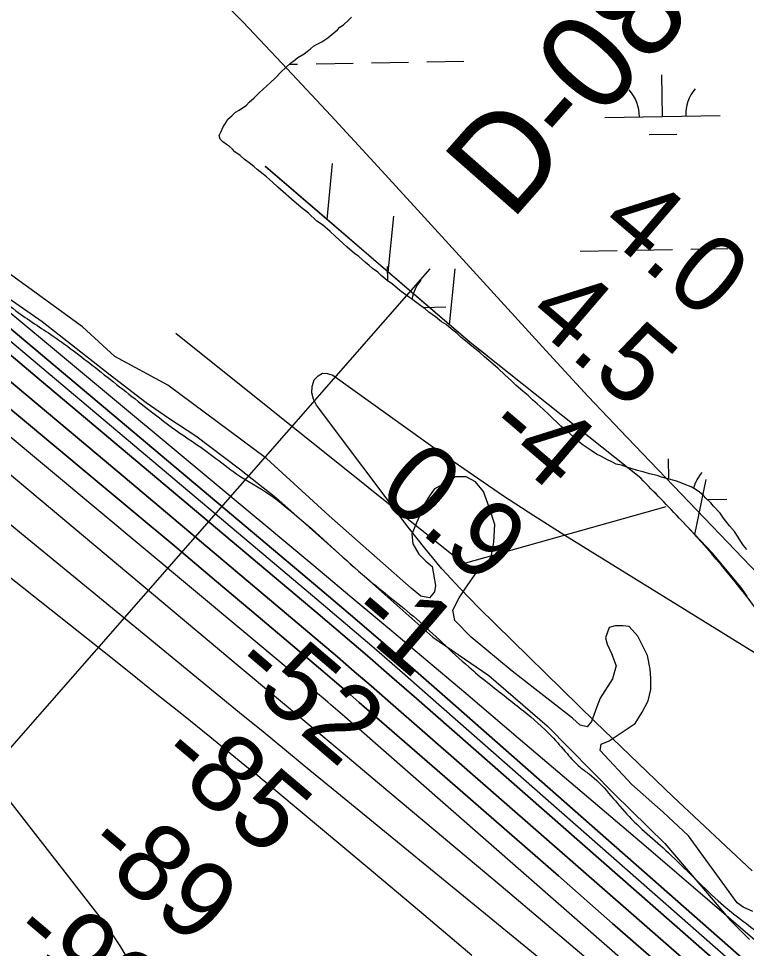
# Model space of a CAD drawing. Extents: x 3887375 to 3925618, y 296674 to 322633.
# Drawn here: x 3894675 to 3895306, y 313327 to 314133 of the extents above; entities that cross this region are included whole.
import ezdxf

# ---------------------------------------------------------------- set-up
doc = ezdxf.new("R2010")
doc.units = 0
for name, color, linetype in [('V-RIVR-EDGE', 7, 'Continuous'), ('V-RIVR-JETY', 7, 'Continuous'), ('V-RIVR-RANG', 7, 'Continuous'), ('V-RIVR-RANG-IDEN', 7, 'Continuous'), ('V-RRAP-FSHR', 7, 'Continuous'), ('V-TOPO-DPTH', 7, 'Continuous'), ('V-TOPO-MAJR', 7, 'Continuous'), ('V-TOPO-MINR', 7, 'Continuous'), ('V-TOPO-SHOR', 7, 'Continuous'), ('V-TOPO-WATR', 7, 'Continuous'), ('V-WETL-SWMP', 7, 'Continuous')]:
    doc.layers.add(name, color=color, linetype=linetype)

msp = doc.modelspace()

# ---------------------------------------------------------------- linework, layer by layer
at = {"layer": 'V-RIVR-EDGE'}
msp.add_spline([(3894279.09, 314238.38), (3894300.17, 314224.38), (3894318.47, 314210.78), (3894328.81, 314199.99), (3894339.15, 314192.4), (3894356.26, 314181.59), (3894374.58, 314173.98), (3894382.14, 314170.37), (3894386.51, 314164.78), (3894397.24, 314152.8), (3894405.19, 314145.6), (3894434.57, 314098.11), (3894440.9, 314079.36), (3894452.8, 314055.82), (3894469.08, 314031.46), (3894480.99, 314016.69), (3894492.13, 314006.3), (3894499.69, 314002.3), (3894505.66, 313998.3), (3894516.39, 313986.31), (3894533.5, 313973.92), (3894554.19, 313961.11), (3894576.07, 313946.71), (3894604.32, 313925.52), (3894627, 313911.51), (3894651.27, 313896.71), (3894673.15, 313879.52), (3894705.37, 313857.52), (3894744.36, 313828.33), (3894786.92, 313794.75), (3894815.16, 313773.55), (3894843.81, 313753.56), (3894864.49, 313737.96), (3894892.75, 313720.36), (3894906.27, 313709.96), (3894922.58, 313696.37), (3894976.66, 313648.01), (3895020.01, 313612.44), (3895065.34, 313570.88), (3895097.95, 313544.49), (3895112.67, 313532.9), (3895136.93, 313510.92), (3895150.44, 313495.74), (3895161.57, 313484.16), (3895169.53, 313478.16), (3895202.12, 313443.41), (3895238.3, 313409.84), (3895281.24, 313368.29), (3895321.02, 313337.1), (3895346.88, 313317.51), (3895405.32, 313261.97), (3895426, 313241.2), (3895440.7, 313224.82), (3895449.44, 313212.44)], degree=3, dxfattribs=at)
at = {"layer": 'V-RIVR-JETY'}
for points in [[(3895311.45, 313358.88), (3895303.14, 313362.65), (3895297.85, 313366.43), (3895255.56, 313424.58), (3895233.66, 313444.96), (3895206.48, 313469.13), (3895179.29, 313498.58), (3895180.05, 313503.87), (3895186.84, 313506.89), (3895209.5, 313521.99), (3895215.54, 313531.81), (3895220.83, 313541.63), (3895223.09, 313551.44), (3895223.09, 313561.26), (3895222.34, 313568.81), (3895220.07, 313580.89), (3895211.76, 313597.51), (3895204.21, 313605.81), (3895198.93, 313606.57), (3895192.13, 313606.57), (3895186.84, 313605.06), (3895183.82, 313596), (3895185.33, 313590.71), (3895189.11, 313582.4), (3895192.88, 313571.83), (3895189.86, 313560.5), (3895179.29, 313543.89), (3895176.27, 313536.34), (3895171.74, 313523.5), (3895167.96, 313518.97), (3895161.92, 313520.48), (3895155.13, 313526.52), (3895103.02, 313567.3), (3895067.53, 313596.75), (3895053.18, 313611.1), (3895051.67, 313620.16), (3895056.96, 313630.74), (3895064.51, 313642.06), (3895072.06, 313652.63), (3895081.12, 313659.43), (3895084.9, 313667.74), (3895087.16, 313679.07), (3895087.92, 313694.17), (3895083.39, 313708.52), (3895078.1, 313722.87), (3895071.3, 313731.17), (3895063, 313735.7), (3895053.93, 313735.7), (3895041.1, 313728.15), (3895035.81, 313725.13), (3895031.28, 313719.09), (3895026.75, 313711.54), (3895024.48, 313705.5), (3895019.95, 313695.68), (3895016.18, 313685.86), (3895016.93, 313677.56), (3895022.22, 313668.49), (3895028.26, 313662.45), (3895033.55, 313657.92), (3895036.57, 313641.31), (3895035.81, 313636.02), (3895031.28, 313630.74), (3895023.73, 313632.25), (3895015.42, 313639.04), (3894944.44, 313701.72), (3894890.06, 313751.56), (3894804.73, 313814.99), (3894758.67, 313839.92), (3894730.72, 313865.59), (3894535.14, 314007.56)], [(3894557.79, 313966.03), (3894695.99, 313870.12), (3894754.89, 313824.06), (3894785.85, 313799.89), (3894805.49, 313786.3), (3894828.9, 313771.2), (3894866.65, 313742.5), (3894898.37, 313717.58), (3894987.48, 313638.29), (3895034.3, 313596.75), (3895056.2, 313581.65), (3895082.63, 313563.53), (3895133.23, 313519.73), (3895191.37, 313460.82), (3895235.17, 313417.78), (3895265.38, 313382.29), (3895291.81, 313351.32), (3895308.42, 313334.71)]]:
    msp.add_lwpolyline(points, dxfattribs=at)
at = {"layer": 'V-RIVR-RANG'}
msp.add_line((3895031.53, 313915.92), (3894557.25, 313374.2), dxfattribs=at)
at = {"layer": 'V-RRAP-FSHR'}
for p, q in [((3894942.57, 313958.54), (3894947.39, 314007.13)), ((3894995.68, 313912.93), (3895000.49, 313961.52)), ((3895048.78, 313867.33), (3895053.59, 313915.92)), ((3895261.17, 313685.55), (3895271.06, 313733.37))]:
    msp.add_line(p, q, dxfattribs=at)
for points in [[(3895214.31, 313734.34), (3895066.45, 313852.15), (3894888.92, 314004.62)], [(3894889.47, 314004.14), (3894888.92, 314004.62)], [(3894942.57, 313958.54), (3894889.47, 314004.15)], [(3894995.68, 313912.93), (3894942.57, 313958.54)], [(3895081.27, 313840.34), (3895066.45, 313852.15), (3895048.78, 313867.33), (3894995.67, 313912.93)], [(3894811.5, 313860.16), (3895060.76, 313660.4), (3895236.38, 313709.88)], [(3895261.17, 313685.55), (3895249.53, 313697.9), (3895231.92, 313716.12), (3895224.84, 313723.44)], [(3895306.48, 313632.29), (3895300.99, 313640.09), (3895276.1, 313669.72), (3895261.17, 313685.56)]]:
    msp.add_lwpolyline(points, dxfattribs=at)
msp.add_spline([(3895382.66, 313514.85), (3895315.81, 313619.05), (3895249.53, 313697.9), (3895214.31, 313734.34)], degree=3, dxfattribs=at)
at = {"layer": 'V-TOPO-DPTH'}
for points in [[(3895356.45, 313608.97), (3895202.61, 313769.6), (3895185.66, 313787.43), (3895168.79, 313805.34), (3895152.06, 313823.38), (3895135.42, 313841.49), (3895020.97, 313966.99), (3894983.49, 314007.86), (3894945.86, 314048.59), (3894907.99, 314089.11), (3894869.98, 314129.49), (3894830.99, 314168.81), (3894790.87, 314206.89), (3894621.93, 314337.77), (3894383.23, 314448.72), (3894091.96, 314544.03), (3893867.05, 314583.12), (3893838.43, 314605.12), (3893809.72, 314626.99), (3893780.94, 314648.78), (3893286.1, 315021.75), (3893269.81, 315033.97), (3893253.49, 315046.13)], [(3895305.16, 313270.77), (3895231.56, 313335.34), (3895157.88, 313399.81), (3894995.3, 313541.84), (3894980.78, 313554.46), (3894966.21, 313567.04), (3894951.59, 313579.53), (3894936.92, 313591.98), (3894833.93, 313678.9), (3894767.68, 313734.72), (3894701.37, 313790.45), (3894634.96, 313846.06), (3894568.48, 313901.59), (3894415.94, 314028.77), (3894397.05, 314044.56), (3894378.18, 314060.37), (3894359.34, 314076.22), (3894340.52, 314092.09), (3893865.37, 314493.75)], [(3893865.37, 314493.75), (3894340.52, 314092.09), (3894359.34, 314076.22), (3894378.18, 314060.37), (3894397.05, 314044.56), (3894415.94, 314028.77), (3894568.48, 313901.59), (3894634.96, 313846.06), (3894701.37, 313790.45), (3894767.68, 313734.72), (3894833.93, 313678.9), (3894936.92, 313591.98), (3894951.59, 313579.53), (3894966.21, 313567.04), (3894980.78, 313554.46), (3894995.3, 313541.84), (3895157.88, 313399.81), (3895231.56, 313335.34), (3895305.16, 313270.77)], [(3895236.78, 313307.47), (3895189.92, 313348.65), (3895143.02, 313389.78), (3895096.04, 313430.82), (3895049.01, 313471.8), (3894970.56, 313540.04), (3894962.7, 313546.84), (3894954.82, 313553.63), (3894946.91, 313560.38), (3894938.99, 313567.11), (3894882.83, 313614.59), (3894846.78, 313645.01), (3894810.69, 313675.38), (3894774.54, 313705.68), (3894738.35, 313735.93), (3894417.97, 314003.19), (3894392.02, 314024.83), (3894366.08, 314046.48), (3894340.14, 314068.13), (3894314.2, 314089.78), (3894102.47, 314266.53)], [(3894102.47, 314266.53), (3894314.2, 314089.78), (3894340.14, 314068.13), (3894366.08, 314046.48), (3894392.02, 314024.83), (3894417.97, 314003.19), (3894738.35, 313735.93), (3894774.54, 313705.68), (3894810.69, 313675.38), (3894846.78, 313645.01), (3894882.83, 313614.59), (3894938.99, 313567.11), (3894946.91, 313560.38), (3894954.82, 313553.63), (3894962.7, 313546.84), (3894970.56, 313540.04), (3895049.01, 313471.8), (3895096.04, 313430.82), (3895143.02, 313389.78), (3895189.92, 313348.65), (3895236.78, 313307.47)], [(3894208.2, 314229.17), (3894366.18, 314094.17), (3894378.08, 314084.04), (3894390.01, 314073.95), (3894401.97, 314063.9), (3894413.96, 314053.88), (3894491.91, 313989), (3894542.85, 313946.52), (3894593.74, 313903.97), (3894644.56, 313861.34), (3894695.32, 313818.64), (3894934.83, 313616.82), (3894956.24, 313598.66), (3894977.59, 313580.42), (3894998.83, 313562.05), (3895019.99, 313543.6), (3895384.8, 313223.59)], [(3894208.2, 314229.17), (3894366.18, 314094.17), (3894378.08, 314084.04), (3894390.01, 314073.95), (3894401.97, 314063.9), (3894413.96, 314053.88), (3894491.91, 313989), (3894542.85, 313946.52), (3894593.74, 313903.97), (3894644.56, 313861.34), (3894695.32, 313818.64), (3894934.83, 313616.82), (3894956.24, 313598.66), (3894977.59, 313580.42), (3894998.83, 313562.05), (3895019.99, 313543.6), (3895384.8, 313223.59)], [(3895602.02, 313054.44), (3895044.64, 313545.3), (3895016.85, 313569.61), (3894988.95, 313593.79), (3894960.89, 313617.78), (3894932.72, 313641.65), (3894530.51, 313980.01), (3894509.11, 313997.98), (3894487.68, 314015.92), (3894466.23, 314033.83), (3894444.75, 314051.71), (3894411.96, 314078.96), (3894406.87, 314083.21), (3894401.8, 314087.48), (3894396.75, 314091.78), (3894391.72, 314096.09), (3894339.08, 314141.49)], [(3894339.08, 314141.49), (3894391.72, 314096.09), (3894396.75, 314091.78), (3894401.8, 314087.48), (3894406.87, 314083.21), (3894411.96, 314078.96), (3894444.75, 314051.71), (3894466.23, 314033.83), (3894487.68, 314015.92), (3894509.11, 313997.98), (3894530.51, 313980.01), (3894932.72, 313641.65), (3894960.89, 313617.78), (3894988.95, 313593.79), (3895016.85, 313569.61), (3895044.64, 313545.3), (3895602.02, 313054.44)], [(3895310.83, 313394.26), (3895242.38, 313458.37), (3895174.76, 313523.38), (3895074.02, 313622.15), (3895057.79, 313638.8), (3895042.09, 313655.91), (3895027.19, 313673.72), (3895012.82, 313691.99), (3894933.47, 313797.74), (3894930.8, 313803.01), (3894929.36, 313808.39), (3894929.77, 313813.94), (3894931.41, 313819.61), (3894934.79, 313823.25), (3894938.54, 313825.39), (3894942.86, 313825.28), (3894947.56, 313823.68), (3895043.48, 313755.06), (3895069.32, 313736.96), (3895095.4, 313719.22), (3895121.82, 313702), (3895148.48, 313685.14), (3895349.93, 313560.54)]]:
    msp.add_lwpolyline(points, dxfattribs=at)
at = {"layer": 'V-TOPO-MAJR'}
msp.add_lwpolyline([(3895553.31, 313005.87), (3894986.85, 313502.45), (3894979.63, 313508.77), (3894972.4, 313515.07), (3894965.16, 313521.37), (3894957.92, 313527.65), (3894945.77, 313538.17), (3894943.41, 313540.21), (3894941.04, 313542.22), (3894932.56, 313549.4), (3894927.13, 313553.99), (3894921.69, 313558.57), (3894916.24, 313563.14), (3894910.79, 313567.7), (3894364.26, 314023.55), (3894359, 314027.93), (3894353.73, 314032.31), (3894348.46, 314036.68), (3894343.18, 314041.04), (3894281.42, 314091.99), (3894245.15, 314121.68), (3894208.72, 314151.19)], dxfattribs=at)
at = {"layer": 'V-TOPO-MINR'}
for points in [[(3895305.16, 313270.77), (3895231.56, 313335.34), (3895157.88, 313399.81), (3894995.3, 313541.84), (3894980.78, 313554.46), (3894966.21, 313567.04), (3894951.59, 313579.53), (3894936.92, 313591.98), (3894833.93, 313678.9), (3894767.68, 313734.72), (3894701.37, 313790.45), (3894634.96, 313846.06), (3894568.48, 313901.59), (3894415.94, 314028.77), (3894397.05, 314044.56), (3894378.18, 314060.37), (3894359.34, 314076.22), (3894340.52, 314092.09), (3893865.37, 314493.75)], [(3895067.88, 313320.76), (3895022.73, 313359.11), (3894977.43, 313397.28), (3894898.35, 313463.48), (3894892.45, 313468.4), (3894886.54, 313473.29), (3894880.61, 313478.16), (3894874.65, 313483), (3894840.99, 313510.29), (3894818.16, 313528.72), (3894795.29, 313547.11), (3894772.37, 313565.43), (3894749.41, 313583.7), (3894294.27, 313944.56), (3894291.14, 313947.03), (3894288, 313949.49), (3894284.85, 313951.93), (3894281.68, 313954.37), (3894259.02, 313971.73), (3894244.46, 313982.76), (3894229.82, 313993.68), (3894215.06, 314004.44), (3894200.22, 314015.1), (3893695.92, 314373.06)], [(3895517.31, 312998.4), (3894948.01, 313464.64), (3894927.73, 313481.26), (3894907.44, 313497.88), (3894887.17, 313514.51), (3894866.89, 313531.15), (3894759.93, 313618.93), (3894686.16, 313679.44), (3894612.35, 313739.9), (3894538.5, 313800.31), (3894464.62, 313860.68), (3894352.53, 313952.21), (3894333.49, 313967.76), (3894314.46, 313983.3), (3894295.43, 313998.84), (3894276.4, 314014.39), (3893851.13, 314361.81)], [(3894770.27, 313317.49), (3894763.49, 313329.15), (3894756.01, 313340.37), (3894748.06, 313351.29), (3894666.09, 313456.8), (3894615.29, 313518.86), (3894562.48, 313579.07), (3894506.67, 313636.5), (3894448.85, 313692.09), (3894255.51, 313868.67), (3894245.73, 313877.4), (3894235.81, 313885.99), (3894225.71, 313894.35), (3894215.48, 313902.56), (3894130.65, 313969.06), (3894077.74, 314010.19), (3894024.6, 314051.01), (3893971.12, 314091.38), (3893917.41, 314131.46), (3893677.86, 314308.63)], [(3895236.78, 313307.47), (3895189.92, 313348.65), (3895143.02, 313389.78), (3895096.04, 313430.82), (3895049.01, 313471.8), (3894970.56, 313540.04), (3894962.7, 313546.84), (3894954.82, 313553.63), (3894946.91, 313560.38), (3894938.99, 313567.11), (3894882.83, 313614.59), (3894846.78, 313645.01), (3894810.69, 313675.38), (3894774.54, 313705.68), (3894738.35, 313735.93), (3894417.97, 314003.19), (3894392.02, 314024.83), (3894366.08, 314046.48), (3894340.14, 314068.13), (3894314.2, 314089.78), (3894102.47, 314266.53)], [(3895384.8, 313223.59), (3895019.99, 313543.6), (3894998.83, 313562.05), (3894977.59, 313580.42), (3894956.24, 313598.66), (3894934.83, 313616.82), (3894695.32, 313818.64), (3894644.56, 313861.34), (3894593.74, 313903.97), (3894542.85, 313946.52), (3894491.91, 313989), (3894413.96, 314053.88), (3894401.97, 314063.9), (3894390.01, 314073.95), (3894378.08, 314084.04), (3894366.18, 314094.17), (3894208.2, 314229.17)], [(3895494.53, 313138.2), (3895032.33, 313544.46), (3895007.85, 313565.83), (3894983.27, 313587.11), (3894958.57, 313608.23), (3894933.77, 313629.24), (3894612.66, 313899.6), (3894576.62, 313929.89), (3894540.54, 313960.13), (3894504.41, 313990.31), (3894468.24, 314020.45), (3894412.96, 314066.42), (3894404.42, 314073.56), (3894395.91, 314080.72), (3894387.43, 314087.92), (3894378.97, 314095.15), (3894287.47, 314173.72)], [(3895172.63, 313313.98), (3895093.31, 313380.93), (3894986.19, 313470.86), (3894956.51, 313495.77), (3894926.82, 313520.68), (3894897.12, 313545.57), (3894867.41, 313570.46), (3894443.8, 313925.24), (3894426.2, 313939.97), (3894408.58, 313954.68), (3894390.95, 313969.37), (3894373.3, 313984.04), (3894355.62, 313998.67), (3894337.9, 314013.26), (3894320.14, 314027.78), (3894302.34, 314042.27), (3894252.33, 314082.81), (3894209.43, 314117.45), (3894166.43, 314151.96)], [(3895602.02, 313054.44), (3895044.64, 313545.3), (3895016.85, 313569.61), (3894988.95, 313593.79), (3894960.89, 313617.78), (3894932.72, 313641.65), (3894530.51, 313980.01), (3894509.11, 313997.98), (3894487.68, 314015.92), (3894466.23, 314033.83), (3894444.75, 314051.71), (3894411.96, 314078.96), (3894406.87, 314083.21), (3894401.8, 314087.48), (3894396.75, 314091.78), (3894391.72, 314096.09), (3894339.08, 314141.49)], [(3895329.44, 313320.08), (3895274.25, 313367.53), (3895218.98, 313414.89), (3895163.6, 313462.12), (3895108.14, 313509.25), (3895062.71, 313547.76), (3895029.87, 313575.52), (3894996.98, 313603.23), (3894964.02, 313630.85), (3894931.01, 313658.42), (3894449, 314059.86), (3894442.12, 314065.6), (3894435.23, 314071.32), (3894428.34, 314077.05), (3894421.45, 314082.77), (3894410.95, 314091.49), (3894409.31, 314092.86), (3894406.06, 314095.62), (3894404.45, 314097.01), (3894388.05, 314111.21), (3894378.23, 314119.7), (3894368.41, 314128.19), (3894358.58, 314136.66)]]:
    msp.add_lwpolyline(points, dxfattribs=at)
at = {"layer": 'V-TOPO-SHOR'}
for points in [[(3894858.02, 314021.86), (3894855.38, 314023.68), (3894852.31, 314025.95), (3894850.12, 314028.21), (3894849.28, 314031.33), (3894850.66, 314034.41), (3894852.5, 314038.83), (3894854.32, 314041.46), (3894856.6, 314045.42), (3894860.21, 314048.48), (3894863.36, 314051.54), (3894866.5, 314053.26), (3894872.78, 314057.61), (3894875.04, 314060.24), (3894879.54, 314064.17), (3894884.05, 314068.54), (3894887.21, 314071.6), (3894893.51, 314077.28), (3894897.57, 314081.21), (3894902.98, 314086.45), (3894906.59, 314089.95), (3894911.1, 314094.32), (3894913.79, 314096.06), (3894917.39, 314099.11), (3894922.77, 314102.14), (3894925.46, 314104.32), (3894928.16, 314106.5), (3894930.86, 314108.67), (3894934, 314110.4), (3894938.03, 314112.56), (3894943.41, 314116.03), (3894948.36, 314120.39), (3894951.51, 314123.01), (3894953.76, 314125.2), (3894956.91, 314127.37), (3894961.42, 314131.74), (3894963.67, 314133.92)], [(3895306.06, 313672.54), (3895303.45, 313676.13), (3895301.72, 313678.82), (3895298.25, 313684.2), (3895295.65, 313688.24), (3895291.28, 313693.19), (3895286.05, 313699.93), (3895283.01, 313703.98), (3895277.33, 313710.28), (3895275.15, 313712.98), (3895270.77, 313717.05), (3895268.59, 313719.3), (3895265.08, 313722.46), (3895262.45, 313724.28), (3895258.05, 313727.01), (3895251.87, 313729.33), (3895248.34, 313730.72), (3895244.36, 313732.11), (3895237.73, 313733.99), (3895232.42, 313735.4), (3895228.45, 313736.8), (3895221.81, 313738.23), (3895217.39, 313739.63), (3895211.63, 313741.05), (3895205.89, 313742.92), (3895202.35, 313743.86), (3895197.5, 313745.71), (3895193.07, 313746.67), (3895188.66, 313748.96), (3895185.58, 313750.34), (3895180.29, 313753.09), (3895175.88, 313755.37), (3895171.49, 313758.55), (3895164.46, 313763.1), (3895160.51, 313766.27), (3895152.62, 313773.5), (3895145.17, 313779.39), (3895142.11, 313782.54), (3895137.73, 313786.61), (3895134.67, 313789.76), (3895129.85, 313794.28), (3895124.59, 313798.8), (3895120.65, 313802.41), (3895116.71, 313806.03), (3895112.33, 313809.65), (3895106.19, 313815.07), (3895102.25, 313818.69), (3895096.56, 313824.1), (3895090.87, 313829.52), (3895086.48, 313833.14), (3895079.03, 313839.47), (3895074.66, 313843.54), (3895068.08, 313848.97), (3895064.13, 313852.14), (3895058.43, 313856.67), (3895055.37, 313859.82), (3895050.1, 313863.9), (3895045.71, 313867.53), (3895041.75, 313869.8), (3895036.49, 313874.33), (3895030.78, 313878.41), (3895027.72, 313881.13), (3895023.76, 313883.85), (3895015.86, 313889.75), (3895013.22, 313891.56), (3895005.75, 313897.01), (3894999.18, 313902.44), (3894994.79, 313905.62), (3894989.53, 313910.14), (3894986.46, 313912.85), (3894982.07, 313916.03), (3894979, 313918.74), (3894975.93, 313921.45), (3894970.24, 313926.42), (3894966.28, 313929.15), (3894960.15, 313934.57), (3894956.21, 313938.19), (3894949.64, 313944.06), (3894945.26, 313948.13), (3894938.69, 313954), (3894933.85, 313957.18), (3894926.41, 313963.96), (3894920.26, 313968.94), (3894911.94, 313976.17), (3894904.48, 313982.51), (3894900.11, 313986.57), (3894895.29, 313991.09), (3894892.66, 313993.35), (3894890.03, 313995.61), (3894887.4, 313997.87), (3894882.14, 314001.95), (3894879.51, 314004.21), (3894876.44, 314006.92), (3894870.73, 314011.01), (3894867.22, 314014.17), (3894862.83, 314017.35), (3894860.65, 314019.6), (3894858.02, 314021.86)]]:
    msp.add_lwpolyline(points, dxfattribs=at)
at = {"layer": 'V-TOPO-WATR'}
for points in [[(3895356.45, 313608.97), (3895202.61, 313769.6), (3895185.66, 313787.43), (3895168.79, 313805.34), (3895152.06, 313823.38), (3895135.42, 313841.49), (3895020.97, 313966.99), (3894983.49, 314007.86), (3894945.86, 314048.59), (3894907.99, 314089.11), (3894869.98, 314129.49), (3894830.99, 314168.81), (3894790.87, 314206.89), (3894621.93, 314337.77), (3894383.23, 314448.72), (3894091.96, 314544.03), (3893867.05, 314583.12), (3893838.43, 314605.12), (3893809.72, 314626.99), (3893780.94, 314648.78), (3893286.1, 315021.75), (3893269.81, 315033.97), (3893253.49, 315046.13)], [(3895310.83, 313394.26), (3895242.38, 313458.37), (3895174.76, 313523.38), (3895074.02, 313622.15), (3895057.79, 313638.8), (3895042.09, 313655.91), (3895027.19, 313673.72), (3895012.82, 313691.99), (3894933.47, 313797.74), (3894930.8, 313803.01), (3894929.36, 313808.39), (3894929.77, 313813.94), (3894931.41, 313819.61), (3894934.79, 313823.25), (3894938.54, 313825.39), (3894942.86, 313825.28), (3894947.56, 313823.68), (3895043.48, 313755.06), (3895069.32, 313736.96), (3895095.4, 313719.22), (3895121.82, 313702), (3895148.48, 313685.14), (3895349.93, 313560.54)]]:
    msp.add_lwpolyline(points, dxfattribs=at)
at = {"layer": 'V-WETL-SWMP'}
for p, q in [((3894909.84, 314093.1), (3894917.1, 314093.23)), ((3894933.09, 314093.5), (3894965.09, 314094.05)), ((3894981.09, 314094.32), (3895013.08, 314094.87)), ((3895029.08, 314095.15), (3895061.08, 314095.7)), ((3895233.24, 314047.9), (3895232.62, 314083.9)), ((3895183.24, 314047.04), (3895283.23, 314048.76)), ((3895221.5, 314032.27), (3895245.5, 314032.68)), ((3895161.82, 313931.23), (3895193.82, 313931.78)), ((3895209.81, 313932.05), (3895241.81, 313932.6)), ((3895257.81, 313932.88), (3895289.8, 313933.42)), ((3894995.18, 313905.33), (3894994.96, 313917.93)), ((3895025.78, 313882.46), (3895045.57, 313882.8)), ((3895238.63, 313733.73), (3895238.33, 313751.27)), ((3895272.07, 313715.85), (3895288.94, 313716.13))]:
    msp.add_line(p, q, dxfattribs=at)
for points in [[(3894866.5, 314053.27), (3894872.78, 314057.61), (3894875.04, 314060.24), (3894879.54, 314064.17), (3894884.05, 314068.54), (3894887.21, 314071.6), (3894893.51, 314077.27), (3894897.57, 314081.21), (3894902.98, 314086.45), (3894906.59, 314089.95), (3894911.1, 314094.32), (3894913.79, 314096.06), (3894917.39, 314099.11), (3894922.77, 314102.14), (3894925.46, 314104.32), (3894928.16, 314106.49), (3894930.86, 314108.67), (3894934, 314110.4), (3894938.03, 314112.56), (3894943.41, 314116.03), (3894948.36, 314120.39), (3894951.51, 314123.01), (3894953.77, 314125.2), (3894956.91, 314127.37), (3894961.42, 314131.74), (3894963.67, 314133.92)], [(3895277.33, 313710.28), (3895275.15, 313712.98), (3895270.77, 313717.05), (3895268.59, 313719.3), (3895265.09, 313722.46), (3895262.45, 313724.28), (3895258.05, 313727.01), (3895251.87, 313729.33), (3895248.34, 313730.72), (3895244.36, 313732.11), (3895237.73, 313733.99), (3895232.42, 313735.4), (3895228.45, 313736.8), (3895221.81, 313738.23), (3895217.39, 313739.63), (3895211.64, 313741.05), (3895205.89, 313742.92), (3895202.35, 313743.86), (3895197.5, 313745.71), (3895193.07, 313746.67), (3895188.66, 313748.96), (3895185.58, 313750.34), (3895180.29, 313753.09), (3895175.88, 313755.37), (3895171.49, 313758.55), (3895164.46, 313763.1), (3895160.51, 313766.27), (3895152.62, 313773.5), (3895145.17, 313779.39), (3895142.11, 313782.54), (3895137.73, 313786.61), (3895134.67, 313789.76), (3895129.85, 313794.28), (3895124.59, 313798.8), (3895120.65, 313802.41), (3895116.71, 313806.03), (3895112.33, 313809.65), (3895106.19, 313815.07), (3895102.25, 313818.69), (3895096.56, 313824.1), (3895090.87, 313829.52), (3895086.48, 313833.14), (3895079.03, 313839.47), (3895074.66, 313843.54), (3895068.08, 313848.97), (3895064.13, 313852.14), (3895058.43, 313856.67), (3895055.37, 313859.83), (3895050.1, 313863.9), (3895045.71, 313867.52), (3895041.75, 313869.8), (3895036.49, 313874.33), (3895030.78, 313878.41), (3895027.71, 313881.12), (3895023.76, 313883.85), (3895015.86, 313889.75), (3895013.22, 313891.56), (3895005.75, 313897.01), (3894999.18, 313902.44), (3894994.79, 313905.61), (3894989.53, 313910.14), (3894986.46, 313912.85), (3894982.07, 313916.03), (3894979, 313918.74), (3894975.93, 313921.45), (3894970.24, 313926.42), (3894966.28, 313929.15), (3894960.15, 313934.57), (3894956.21, 313938.19), (3894949.64, 313944.06), (3894945.26, 313948.13), (3894938.69, 313954), (3894933.85, 313957.18), (3894926.41, 313963.96), (3894920.26, 313968.94), (3894911.94, 313976.18), (3894904.48, 313982.51), (3894900.11, 313986.57), (3894895.29, 313991.09), (3894892.66, 313993.35), (3894890.03, 313995.61), (3894887.4, 313997.87), (3894882.14, 314001.95), (3894879.51, 314004.21), (3894876.44, 314006.92), (3894870.73, 314011.01), (3894867.23, 314014.17), (3894862.83, 314017.35), (3894860.65, 314019.6), (3894858.02, 314021.86), (3894855.38, 314023.68), (3894852.31, 314025.95), (3894850.12, 314028.2), (3894849.28, 314031.33), (3894850.66, 314034.41), (3894852.51, 314038.83), (3894854.32, 314041.46), (3894856.6, 314045.42), (3894860.21, 314048.48), (3894863.36, 314051.54), (3894866.5, 314053.27)], [(3895306.06, 313672.54), (3895303.45, 313676.13), (3895301.72, 313678.82), (3895298.25, 313684.2), (3895295.65, 313688.24), (3895291.28, 313693.19), (3895286.06, 313699.93), (3895283.01, 313703.98), (3895277.33, 313710.28)]]:
    msp.add_lwpolyline(points, dxfattribs=at)
for centre, start, end in [((3895177.99, 314047.43), 0.21154, 41.7552), ((3895288.46, 314049.33), 140.21154, 181.75519), ((3895050.8, 313883.36), 140.21154, 169.871), ((3895294.17, 313716.7), 140.21154, 165.1423)]:
    msp.add_arc(centre, 35.25, start, end, dxfattribs=at)

# ---------------------------------------------------------------- texts
at = {"layer": 'V-RIVR-RANG'}
for s, rotation, p in [('4.0', 319.49833, (3895176.25, 313950.75)), ('4.5', 319.49833, (3895113.7, 313872.66)), ('-4', 319.49833, (3895076.62, 313772.82)), ('0.9', 319.49833, (3894983.98, 313720.44)), ('-1', 319.49833, (3894957.53, 313611.52)), ('-52', 319.49833, (3894856.46, 313566.33)), ('-85', 319.78128, (3894793.18, 313488.35)), ('-89', 319.78128, (3894729.83, 313410.96)), ('-90', 319.78128, (3894665.07, 313334.76))]:
    msp.add_text(s, height=67, rotation=rotation, dxfattribs=at).set_placement(p)
at = {"layer": 'V-RIVR-RANG-IDEN'}
msp.add_text('D-080', height=83, rotation=48.65633, dxfattribs=at).set_placement((3895101.89, 313956.33))

doc.saveas('drawing.dxf')
